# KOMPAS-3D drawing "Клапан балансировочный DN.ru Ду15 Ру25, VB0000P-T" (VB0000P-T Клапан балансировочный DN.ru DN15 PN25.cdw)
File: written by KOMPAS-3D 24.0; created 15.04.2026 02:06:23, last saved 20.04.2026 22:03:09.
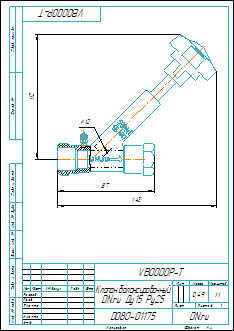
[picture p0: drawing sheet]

Document properties: Автор: DN.ru; Форматы листов документа: A4; Полное имя файла: VB0000P-T DN15 PN25 Клапан балансировочный DN.ru.cdw; Масса: 0.49; Наименование: Клапан балансировочный DN.ru Ду15 Ру25; Количество листов документа: 1; Примечание: D080-01175

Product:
- Part/product: Клапан балансировочный DN.ru Ду15 Ру25  | designation VB0000P-T
    Масса: 0.49
    Раздел спецификации: Прочие изделия
    Форматы листов документа: A4
    Примечание: D080-01175

Views: Вид 1, Местный разрез 1, Вид:1
Referenced files in C:\Работа\VB0000P-T DN X PN 25 Клапан балансировочный DN.ru\DN15\: VB0000P-T DN15 PN25 Клапан балансировочный DN.ru.m3d
Referenced files in E:\Работа\Зайцев\АУТСОРС\Диман\Балансировка\VB0000P-T Клапан балансировочный DN.ru Ду15-50 Ру25\DN15\: VB0000P-T Клапан балансировочный DN.ru DN15 PN25.m3d
Referenced files in C:\Program Files\ASCON\KOMPAS-3D v24\Templates\: Чертеж_DN.ru.cdt
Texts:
  VB0000P-T
  Чертеж_DN.ru.cdt
  Клапан балансировочный
  DN.ru Ду15 Ру25
  Клапан балансировочный DN.ru Ду15 Ру25
  VB0000P-T Клапан балансировочный DN.ru Ду15 Ру25
Dimensions and other numbers on the sheet: 0; 3; 2; 4; 143; 112; 87; 1:1; 1; 0,49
